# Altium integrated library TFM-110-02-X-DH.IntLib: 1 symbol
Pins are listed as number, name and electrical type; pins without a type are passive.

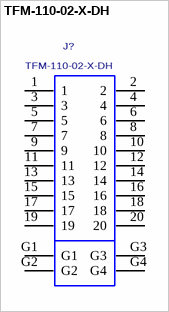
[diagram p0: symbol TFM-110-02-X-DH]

## TFM-110-02-X-DH
designator J?
0.050" DOUBLE HORIZONTAL TERMINAL STRIP.; MANUFACTURER: SAMTEC
footprint TFM-110-02-X-DH
pins: 1, 2, 3, 4, 5, 6, 7, 8, 9, 10, 11, 12, 13, 14, 15, 16, 17, 18, 19, 20, G1, G2, G3, G4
